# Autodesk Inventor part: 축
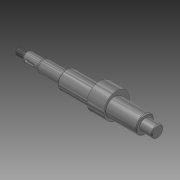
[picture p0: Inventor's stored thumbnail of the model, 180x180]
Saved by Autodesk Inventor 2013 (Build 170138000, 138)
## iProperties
Created: 2015-12
Part Number: 축
Document SubType Name: Modeling
Designer: mdu
Density: 7.86 g/cm^3
Material: 강철, 연강
Mass: 494.669 g
Surface Area: 129.298 cm^2
Volume: 62.935 cm^3
Author: mdu
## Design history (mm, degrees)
sketch "스케치1"
  geometry: L1 (62, 100.9)-(62, 67.1) reference; L2 (51, 101.2)-(51, 84) reference; L3 (-51, 84)-(-51, 101.2) reference; L4 (-62, 67.1)-(-62, 100.9) reference; L5 (-51.6, 91.5)-(-61.4, 91.5) reference; L6 (51.6, 91.5)-(61.4, 91.5) reference; L7 (67, 84)-(-114, 84); L8 (-77, 64.201)-(-77, 103.799) reference; L9 (67, 84)-(67, 91.5); L10 (67, 91.5)-(51, 91.5); L11 (51, 91.5)-(51, 95.5); L12 (51, 95.5)-(-51, 95.5); L13 (-51, 95.5)-(-51, 91.5); L14 (-51, 91.5)-(-82, 91.5); L15 (-82, 91.5)-(-82, 90); L16 (-82, 90)-(-102, 90); L17 (-102, 90)-(-102, 87); L18 (-103.5, 88)-(-114, 88); L19 (-114, 88)-(-114, 84); L20 (-102, 87)-(-103.5, 87); L21 (-103.5, 87)-(-103.5, 88); 2 further points
  constraints: 32 end point, 7 parallel, 6 point on line, 5 perpendicular, 2 collinear, 2 horizontal, 1 midpoint, 4 other
  dimensions: "d0" = 5 distance from line of L7.start L1; "d2" = 5 distance between parallel lines of L15 L8; "d3" = 23 diameter of L12 L7; "d4" = 12 diameter of L16 L7; "d5" = 1.5 distance of L17.end L20.end; "d6" = 6 diameter of L20 L7; "d7" = 20 distance of L15.end L16.end; "d8" = 12 distance between parallel lines of L17 L19; "d9" = 8 diameter of L18 L7
revolve "회전1" sketch "스케치1" stored, may be unused: angle "d10" = 90 deg
sketch "스케치2"
  geometry: C1 r 11.5 at (84, 0) reference; C2 r 11.5 at (84, 0) reference; C3 r 16.5 at (87, 0); 1 further point
  constraints: 1 centre point, 1 horizontal alignment
  dimensions: "d11" = 33 diameter of C3; "d12" = 3 distance of C3.centre C1.centre
extrude "돌출1" join sketch "스케치2" stored distance "d13" = 22; taper "d14" = 0 deg
chamfer "모따기1" distance "d15" = 1; stored, may be unused: second distance "d16" = 2, angle "d17" = 45 deg
feature "스레드1" dims "d18" = 10, "d19" = 0
node "작업 평면1"
sketch "스케치3"
  geometry: L1 (-5, -2)-(3, -2); L2 (3, 2)-(-5, 2); L3 (-10, -5)-(-10, 5) reference; A1 r 2 centre (3, 0) between (3, -2) and (3, 2); A2 r 2 centre (-5, 0) between (-5, 2) and (-5, -2); 2 further points
  constraints: 4 end point, 4 point on circle, 4 tangent, 2 centre point, 1 horizontal, 1 horizontal alignment, 1 midpoint, 1 parallel
  dimensions: "d20" = 4 distance between parallel lines of L1 L2; "d21" = 12 dimension on A1 A2; "d22" = 3 distance edge to line of A2 L3
extrude "돌출2" cut sketch "스케치3" distance "d23" = 2.5; taper "d24" = 0 deg
fillet "모깎기1" dims "d25" = 0.3
fillet "모깎기2" dims "d26" = 3
node "솔리드1"
node "참조1"
node "참조2"
node "참조3"
node "참조4"
node "참조5"
node "투영된 루프1"
